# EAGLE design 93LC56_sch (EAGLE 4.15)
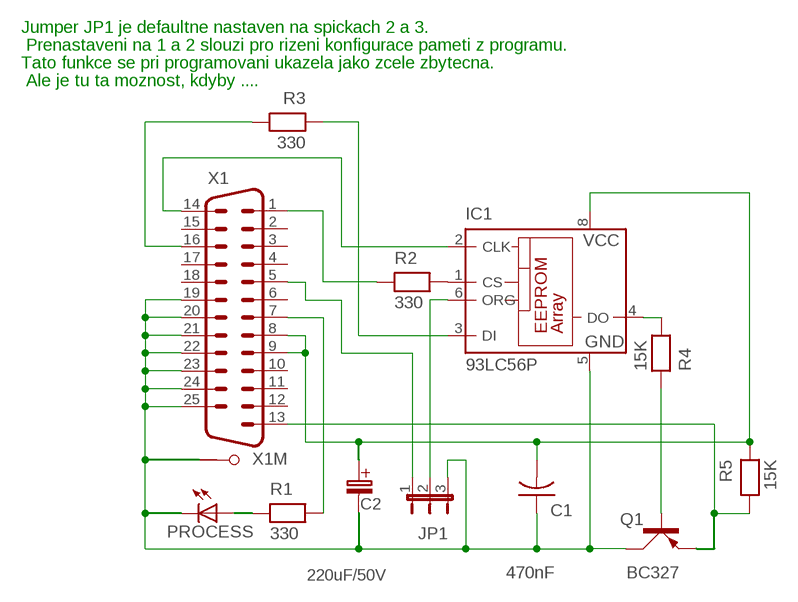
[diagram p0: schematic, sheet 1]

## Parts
C1  470nF  CAP-7,5  [C-7,5]
C2  220uF/50V  C-ELEKTROLYT_5  [C-EL_5]
IC1  93LC56P  [DIL8]
JP1  JP2E  [JP2]
PROCESS  LED3MM  [LED3MM]
Q1  BC327  [SOT54A]
R1  330  RESEU-10  [R-10]
R2  330  RESEU-10  [R-10]
R3  330  RESEU-10  [R-10]
R4  15K  RESEU-10  [R-10]
R5  15K  RESEU-10  [R-10]
X1  M25HP  [M25HP]

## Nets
GND: C1.1 C2.C-(C_EL-) IC1.5(GND) JP1.3 PROCESS.K(C) Q1.C X1.19 X1.20 X1.21 X1.22 X1.23 X1.24 X1.25 X1.G1
N$1: IC1.1(CS) R2.2
N$2: R3.2 X1.16
N$3: Q1.B R4.1
N$4: Q1.E R5.2 X1.13
N$5: PROCESS.A R1.1
N$6: R1.2 X1.7
N$7: IC1.6(ORG) JP1.2
N$9: IC1.2(CLK) X1.14
N$10: R2.1 X1.1
N$11: JP1.1 X1.5
N$12: IC1.3(DI) R3.1
N$13: IC1.4(DO) R4.2
VCC: C1.2 C2.C+(C_EL+) IC1.8(VCC) R5.1 X1.8 X1.9
Unconnected: IC1.7(NU) X1.2 X1.3 X1.4 X1.6 X1.10 X1.11 X1.12 X1.15 X1.17 X1.18 X1.G2

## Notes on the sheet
- Jumper JP1 je defaultne nastaven na spickach 2 a 3.
- Prenastaveni na 1 a 2 slouzi pro rizeni konfigurace pameti z programu.
- Tato funkce se pri programovani ukazela jako zcele zbytecna.
- Ale je tu ta moznost, kdyby ....

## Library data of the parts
C1 = discrete:CAP-7,5
C2 = #hacesoft:C-ELEKTROLYT: Kondenzator - elektrolyticky
IC1 = microchip:93*: Serial EPROM 1 K/2 K/4 K, low voltage, Microwire
JP1 = jumper:JP2E: JUMPER
PROCESS = led:LED: LED
Q1 = transistor-small-signal:BC327: PNP TRANSISTOR
R1-R5 = discrete:RESEU-10
X1 = con-subd:M25HP: SUB-D

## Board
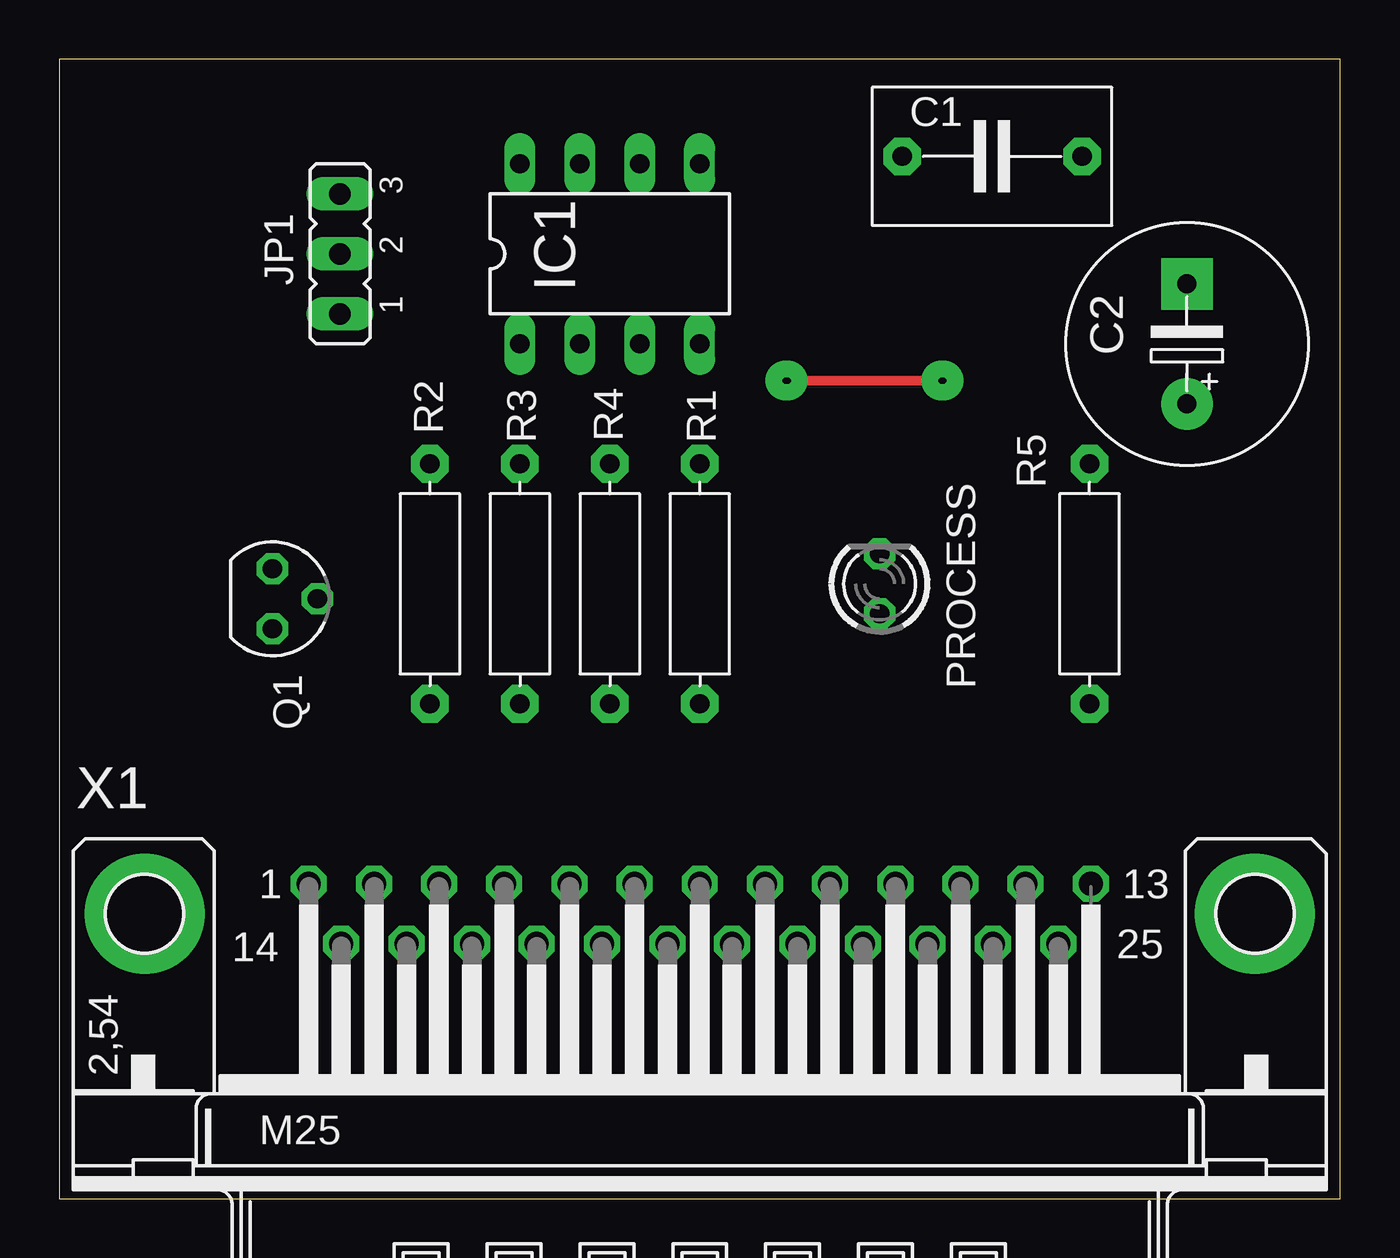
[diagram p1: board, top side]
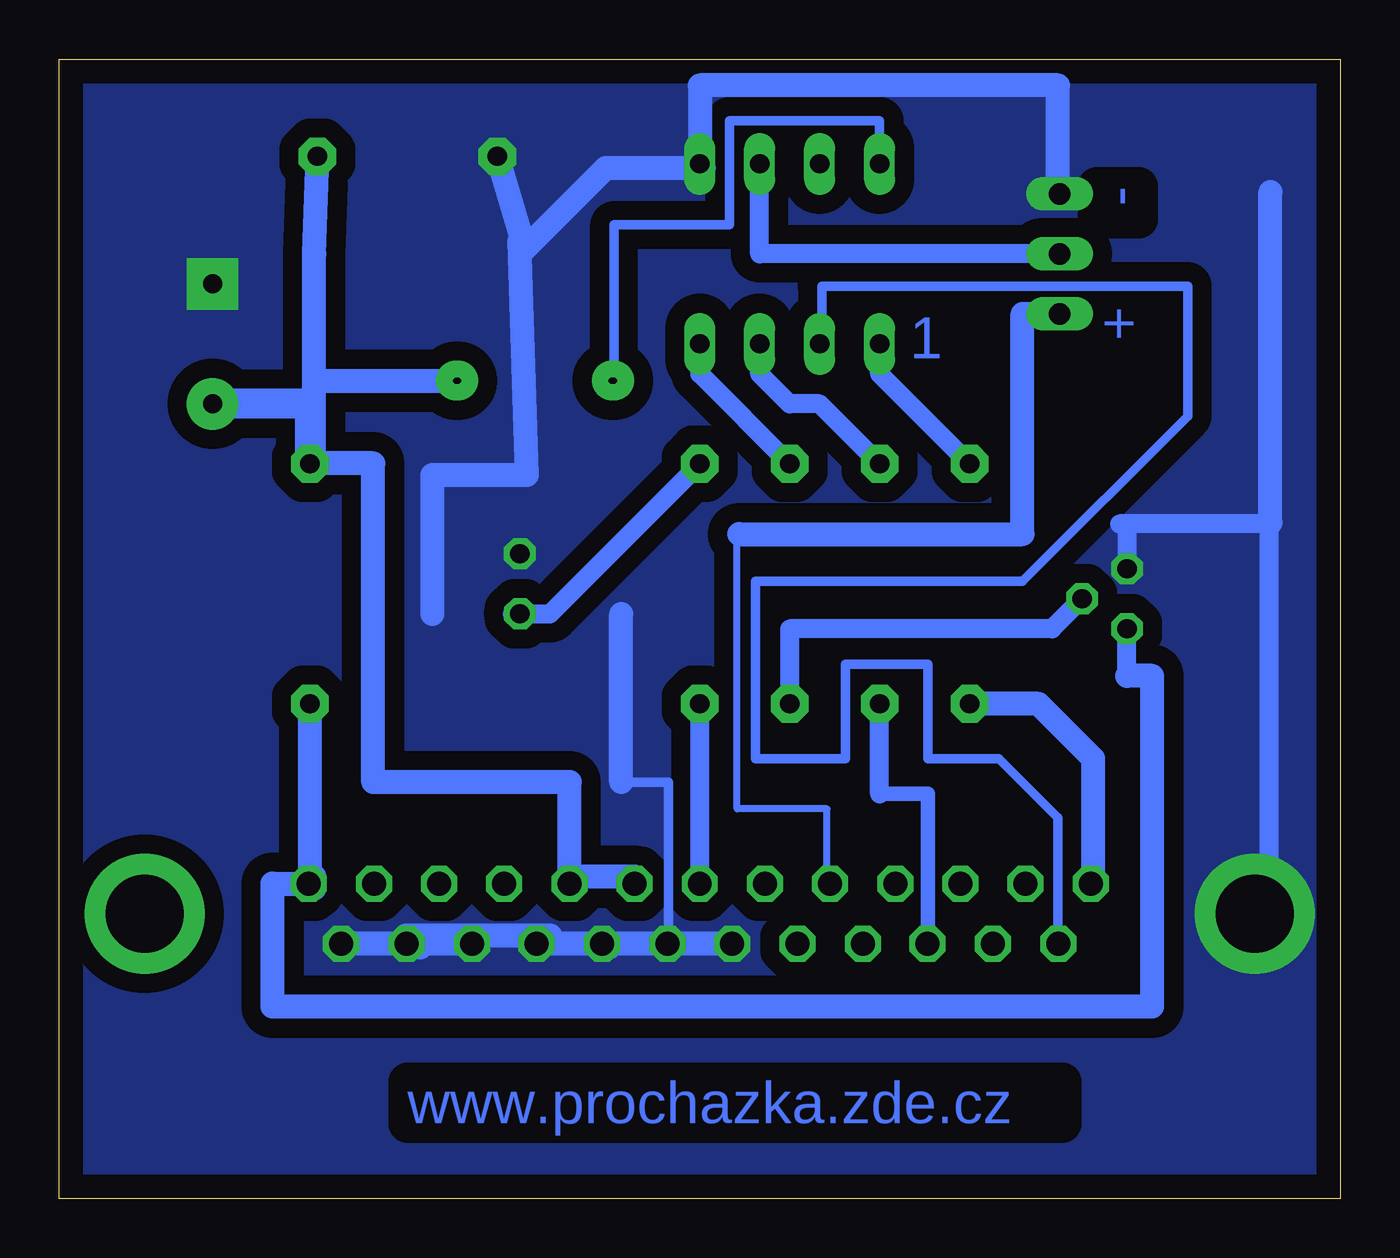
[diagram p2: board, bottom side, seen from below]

Size 54.28 x 48.25 mm. Coordinates in mm from the lower left corner, seen from the top.
Outline: 0,0 54.28,0 54.28,48.25 0,48.25 0,0
Copper layers (1*16): Top 0.035mm / dielectric 1.5mm / Bottom 0.035mm
Design rules "default": minimum track width 10mil, minimum drill 24mil, track to track 8mil, track to pad 8mil, pad to pad 8mil, via to via 8mil, smd to smd 8mil, copper to edge 40mil, drill to drill 8mil, minimum pad ring 10mil, minimum via ring 8mil, stop-mask expansion 4mil, vias tented up to drill 0mil, thermal gap 10mil

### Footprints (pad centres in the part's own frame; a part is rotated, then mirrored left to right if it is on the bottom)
C-7,5 = drill 0.813 pad 1.6 octagon: 1 -3.81,0; 2 3.81,0
C-EL_5 = drill 0.813 pad 2.184 round: C+ -2.54,0 | drill 0.813 pad 2.184 square: C- 2.54,0
DIL8 = drill 0.813 long: 1 -3.81,-3.81; 2 -1.27,-3.81; 3 1.27,-3.81; 4 3.81,-3.81; 5 3.81,3.81; 6 1.27,3.81; 7 -1.27,3.81; 8 -3.81,3.81
JP2 = drill 0.914 long: 1 -2.54,0; 2 0,0; 3 2.54,0
LED3MM = drill 0.813 octagon: A -1.27,0; K 1.27,0
SOT54A = drill 0.813 octagon: B 0,1.905; C -1.27,0; E 1.27,0
R-10 = drill 0.813 pad 1.6 octagon: 1 -5.08,0; 2 5.08,0
M25HP = drill 1.016 octagon: 1 -16.561,1.27; 2 -13.792,1.27; 3 -11.049,1.27; 4 -8.28,1.27; 5 -5.512,1.27; 6 -2.769,1.27; 7 0,1.27; 8 2.769,1.27; 9 5.512,1.27; 10 8.28,1.27; 11 11.049,1.27; 12 13.792,1.27; 13 16.561,1.27; 14 -15.189,-1.27; 15 -12.421,-1.27; 16 -9.652,-1.27; 17 -6.909,-1.27; 18 -4.14,-1.27; 19 -1.372,-1.27; 20 1.372,-1.27; 21 4.14,-1.27; 22 6.909,-1.27; 23 9.652,-1.27; 24 12.421,-1.27; 25 15.189,-1.27 | drill 3.302 pad 5.08 round: G1 -23.52,0; G2 23.52,0

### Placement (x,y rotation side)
C1  39.52,44.13 0 top
C2  47.78,36.19 90 top
IC1  23.33,40 0 top
JP1  11.9,40 90 top
PROCESS  34.76,26.03 90 top
Q1  9.04,25.39 270 top
R1  27.14,26.03 270 top
R2  15.71,26.03 90 top
R3  19.52,26.03 270 top
R4  23.33,26.03 90 top
R5  43.65,26.03 270 top
X1  27.14,12.06 0 top

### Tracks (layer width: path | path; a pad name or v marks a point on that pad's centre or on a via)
GND
  Bottom 0.406: 30.47,17.63 28.47,17.63 28.47,10.79
  Bottom 0.813: 3.01,12.06 3.01,28.57 9.04,28.57 | 9.04,28.57 9.36,28.57 | 9.04,28.57 Q1.C
  Bottom 1.016: 34.55,40.21 31.13,43.63 26.97,43.63 26.97,43.64 IC1.5 27.14,47.13 11.97,47.13 11.97,42.63 11.9,42.63 JP1.3 | 34.55,40.21 C1.1 | 3.01,28.57 3.01,28.63 2.97,28.63 2.97,42.63 | 38.47,24.76 38.47,30.63 34.47,30.63 34.79,40.53 34.55,40.21 | 28.47,10.79 X1.20 30.97,10.79 | X1.19 28.47,10.79 | 28.47,10.79 28.47,10.63 | 30.97,10.79 X1.21 33.47,10.79 | 30.97,10.79 30.97,10.63 | 33.47,10.79 33.97,10.79 | 33.97,10.79 X1.22 | 33.97,10.79 33.97,10.63 | 38.97,10.79 X1.24 | X1.24 X1.25 | 36.97,10.79 X1.23 36.79,11.13 33.47,11.13 33.47,10.79 | 36.97,10.79 38.97,10.79 | 38.97,10.79 38.97,10.63 | 30.47,17.63 30.47,24.76 | 36.97,10.79 36.97,11.13 39.56,11.13 X1.24
  pour Bottom (isolate 0.813, no thermals): 0.17,48.53 54.37,48.53 54.37,-0.27 0.17,-0.27
N$1
  Bottom 0.813: IC1.1 19.52,34.92 R2.2
N$2
  Bottom 0.61: X1.16 17.47,10.79 17.47,17.14 19.52,17.14
  Bottom 0.813: 19.52,17.14 R3.2
N$3
  Bottom 0.813: R4.1 23.33,24.12 12.22,24.12 Q1.B
N$4
  Bottom 0.813: 9.04,22.13 Q1.E
  Bottom 1.016: 43.65,13.13 43.7,13.13 X1.13 | 43.65,13.33 43.65,13.13 | 43.65,13.33 R5.2 | 43.65,13.13 43.47,13.13 | X1.13 43.7,13.63 43.47,13.63 | 9.04,22.13 7.97,22.13 7.97,8.13 45.24,8.13 45.24,13.33 43.65,13.33 | 43.65,13.33 X1.13
N$5
  Bottom 0.813: 35.08,24.76 PROCESS.A 33.49,24.76 R1.1
N$6
  Bottom 0.813: X1.7 R1.2
N$7
  Bottom 0.813: JP1.2 24.6,40 IC1.6
N$9
  Bottom 0.406: X1.14 11.97,10.79 11.97,16.13 14.47,18.63 17.47,18.63 17.47,22.63 20.97,22.63 20.97,18.63 24.77,18.63 24.77,26.13 13.47,26.13 6.47,33.13 6.47,38.63 21.97,38.63 21.97,36.13 22.06,36.13 IC1.2
N$10
  Bottom 1.016: R2.1 12.79,20.95 10.47,18.63 10.47,13.44 X1.1
N$11
  Bottom 0.305: 25.47,28.13 25.55,28.13 25.55,16.5 21.74,16.5 21.74,13.33 X1.5
  Bottom 1.016: JP1.1 13.47,37.46 13.47,28.13 25.47,28.13
N$12
  Bottom 0.813: IC1.3 24.6,34.92 23.33,33.65 22.06,33.65 R3.1
N$13
  Bottom 0.813: IC1.4 27.14,34.92 R4.2
N$14  (via drill 0.25 pad 1.68)
  other vias: 30.87,34.63
N$15  (via drill 0.25 pad 1.68)
  other vias: 37.47,34.63
VCC  (via drill 0.25 pad 1.68)
  Top 0.406: v37.37,34.63 v30.77,34.63
  Bottom 0.406: IC1.8 19.52,45.63 25.87,45.63 25.87,41.23 30.77,41.23 v30.77,34.63
  Bottom 1.016: R5.1 43.47,31.11 43.47,31.13 | C1.2 43.47,40 43.47,34.63 | 43.47,31.13 43.47,34.63 | X1.8 29.91,13.63 32.65,13.63 X1.9 32.65,17.63 40.97,17.63 40.97,31.13 43.47,31.13 | 43.47,34.63 v37.37,34.63
  Bottom 1.27: C2.C+ 43.65,33.65 R5.1

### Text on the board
Bottom: - | - | + | 1 | www.prochazka.zde.cz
